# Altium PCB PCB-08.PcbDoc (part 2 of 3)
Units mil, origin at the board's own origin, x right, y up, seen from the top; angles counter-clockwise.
Board outline 2372.23 x 1978.53 mil, 4 copper layers (Top Layer, Plane-1, Plane-2, Bottom Layer), stack 84.834 mil thick; 206 components, 83 nets, 492 pads, 242 vias.
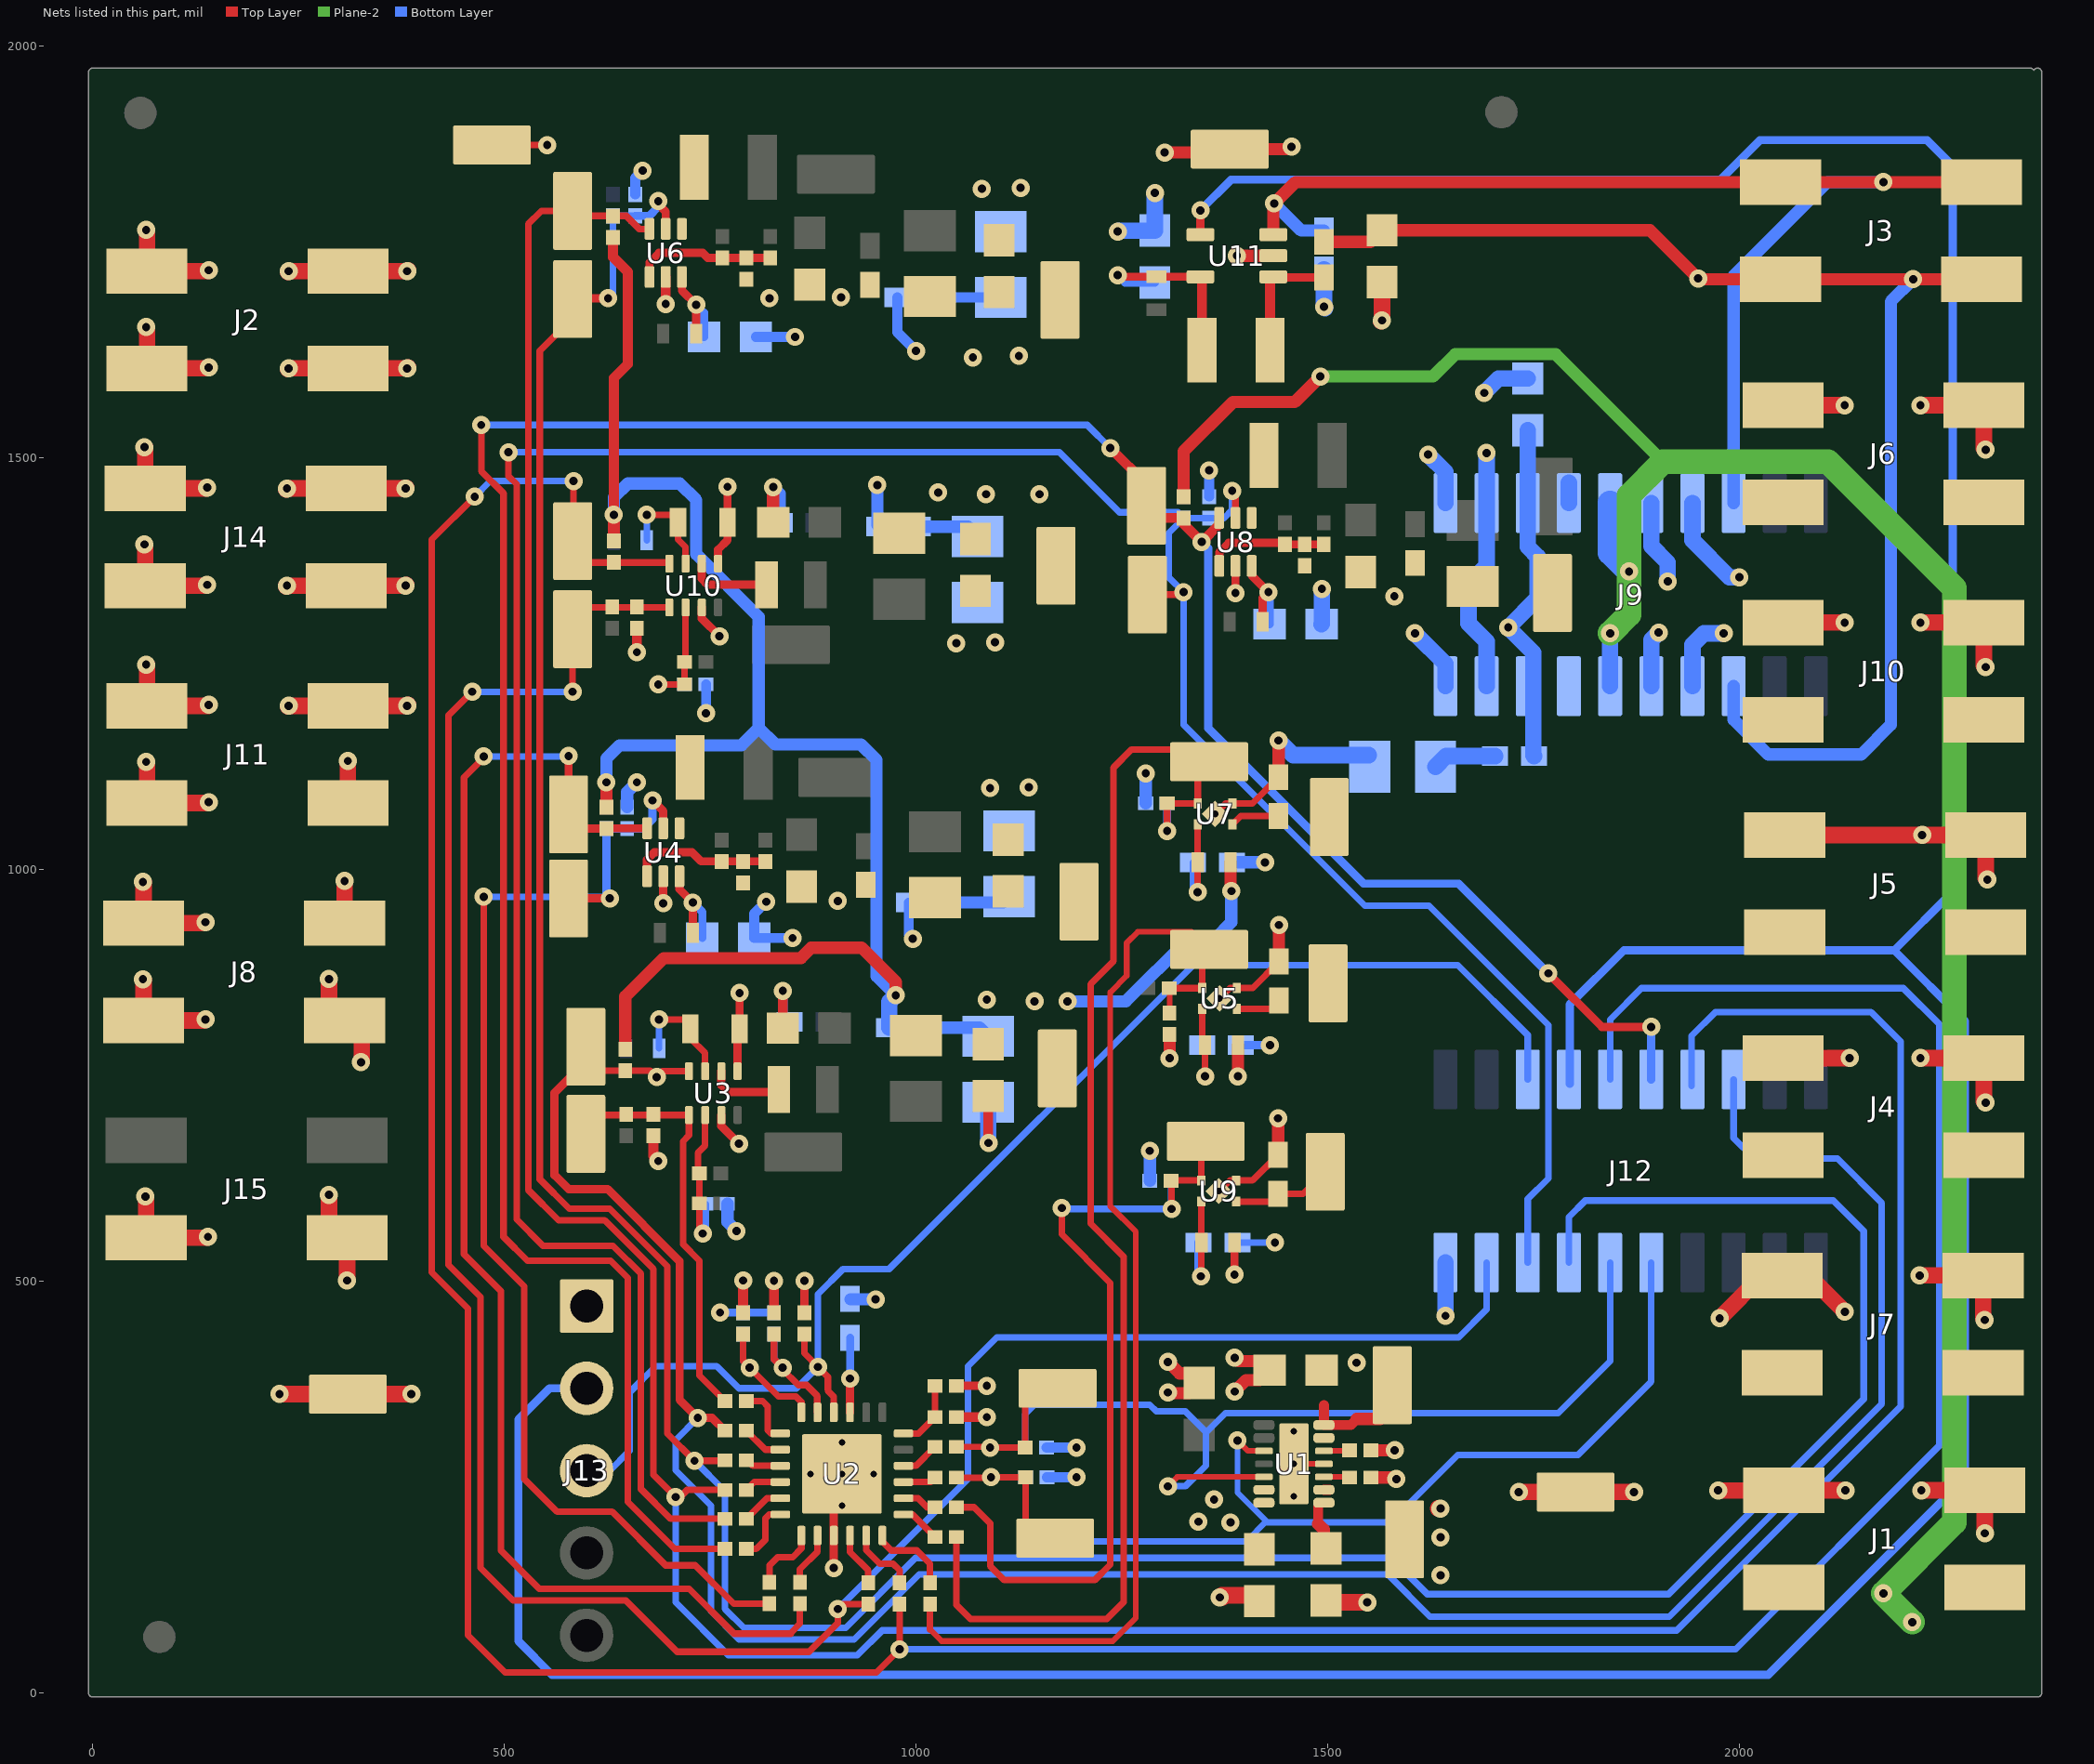
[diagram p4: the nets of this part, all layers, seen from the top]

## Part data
C1 C10 C13 C16 C20: library part CMP-0006203-2, "CAP, CERM, 0.01 uF, 10 V, +/- 10%, X7R, 0402", Cap_Case=0402, Manufacturer=AVX, Supplier Part Number 1=478-7890-1-ND, TempCo=X7R, Tolerance_%=10%, Value1=Unknown, Value2=10V, ValueDisplayed=0.01uF
C2 C11 C14 C17 C21: library part CMP-0007318-5, "CAP, CERM, 10 uF, 10 V, +/- 20%, X5R, 0603", Cap_Case=0603, Manufacturer=MuRata, TempCo=X5R, Tolerance_%=20%, Value1=Unknown, Value2=10V, ValueDisplayed=10uF
C3 C12 C15 C18 C22: library part CMP-0078699-1, "CAP, CERM, 47 µF, 10 V,+/- 20%, X5R, 0805", Cap_Case=0805, Manufacturer=MuRata, Supplier Part Number 1=490-9961-1-ND, TempCo=X5R, Tolerance_%=20%, Value2=10V, ValueDisplayed=47µF
C4: library part CMP-0007379-4, "CAP, CERM, 1 uF, 16 V, +/- 10%, X7R, 0603", Cap_Case=0603, Manufacturer=MuRata, Supplier Part Number 1=490-3900-1-ND, TempCo=X7R, Tolerance_%=10%, Value1="0.011 ohm", Value2=16V, ValueDisplayed=1uF
C5 C6 C25 C27 C32 C37 C42 C45: library part CMP-0064936-4, "CAP, CERM, 4.7 uF, 16 V,+/- 10%, X7R, 0603", Cap_Case=0603, Manufacturer=MuRata, TempCo=X7R, Tolerance_%=10%, Value1=Unknown, Value2=16V, ValueDisplayed=4.7uF
C7: library part CMP-0007365-4, "CAP, CERM, 1 uF, 10 V, +/- 10%, X7R, 0603", Cap_Case=0603, Manufacturer=MuRata, Supplier Part Number 1=490-3899-1-ND, TempCo=X7R, Tolerance_%=10%, Value1="0.011 ohm", Value2=10V, ValueDisplayed=1uF
C8 C9: library part CMP-0009636-3, "CAP, CERM, 1000 pF, 25 V, +/- 10%, X5R, 0201", Cap_Case=0201, Manufacturer=TDK, Supplier Part Number 1=445-1790-1-ND, TempCo=X5R, Tolerance_%=10%, Value1=Unknown, Value2=25V, ValueDisplayed=1000pF
C19: library part CMP-0064927-2, "CAP, CERM, 1 uF, 10 V,+/- 20%, X5R, 0402", Cap_Case=0402, Manufacturer=MuRata, Supplier Part Number 1=490-5409-1-ND, TempCo=X5R, Tolerance_%=20%, Value1=Unknown, Value2=10V, ValueDisplayed=1uF
C23 C41: library part CMP-0009765-1, "CAP, CERM, 120 pF, 25 V, +/- 10%, X7R, 0201", Cap_Case=0201, Manufacturer=MuRata, Supplier Part Number 1=490-3173-1-ND, TempCo=X7R, Tolerance_%=10%, Value1=Unknown, Value2=25V, ValueDisplayed=120pF
C24 C29 C36: library part CMP-0009669-4, "CAP, CERM, 6.8 pF, 50 V, +/- 2%, C0G/NP0, 0201", Cap_Case=0201, Manufacturer=MuRata, Supplier Part Number 1=GRM0335C1H6R8BA01D-ND, TempCo=C0G/NP0, Tolerance_%=2%, Value1=Unknown, Value2=50V, ValueDisplayed=6.8pF
C26 C28 C33 C38 C43: library part CMP-0007497-5, "CAP, CERM, 10 uF, 10 V, +/- 20%, X7R, 0603", Cap_Case=0603, Manufacturer=MuRata, Supplier Part Number 1=81-GRM188Z71A106MA3D, TempCo=X7R, Tolerance_%=20%, Value1=Unknown, Value2=10V, ValueDisplayed=10uF
C30 C31 C34 C35 C39 C40: library part CMP-0006563-2, "CAP, CERM, 1 uF, 10 V, +/- 10%, X5R, 0402", Cap_Case=0402, Manufacturer=MuRata, Supplier Part Number 1=490-3890-1-ND, TempCo=X5R, Tolerance_%=10%, Value1=Unknown, Value2=10V, ValueDisplayed=1uF
C44: library part CMP-0007052-4, "CAP, CERM, 1 uF, 35 V, +/- 10%, X7R, 0603", Cap_Case=0603, Manufacturer=TDK, Supplier Part Number 1=445-7414-1-ND, TempCo=X7R, Tolerance_%=10%, Value1=Unknown, Value2=35V, ValueDisplayed=1uF
D1: library part CMP-0028616-2, "Diode, Schottky, 40 V, 0.25 A, SOD-523", Manufacturer="ON Semiconductor", Supplier Part Number 1=NSR0240V2T1GOSCT-ND, Value1=0.25A, Value2=0.7V
FID1 FID2 FID3 FID4 FID5 FID6: "Fiducial mark.  There is nothing to buy or mount.", Manufacturer=N/A
H1 H2 H3 H4: "Bumpon, Hemisphere, 0.44 X 0.20, Clear", Manufacturer=3M, Supplier Part Number 1=SJ5303-7-ND
J1 J2 J3 J4 J5 J6 J7 J8 J10 J11 J14 J15: library part CMP-0075342-1, "Terminal Block, 3mm, 2-pole, Tin, SMD", Color=White, Current_A=3A, Manufacturer=WAGO, Supplier Part Number 1=38Y8605
J9 J12: library part CMP-0081743-1, "Receptacle, 1.27mm, 10x2, Gold with Tin tail, SMT", Color=Black, Current_A=3.1A, Manufacturer=Samtec, Supplier Part Number 1=SAM9848-ND
J13: library part CMP-0075485-1, "Header, 100mil, 5x1, Gold, TH", Manufacturer=Samtec, Supplier Part Number 1=SAM8737-ND
L1 L2 L3 L4 L5: library part CMP-0003136-1, "Ferrite Bead, 600 ohm @ 100 MHz, 2.1 A, 0805", Manufacturer="Wurth Elektronik", Supplier Part Number 1=732-6126-1-ND, Value1="0.043 ohm", Value2=2.1A, ValueDisplayed="600 ohm"
L6 L10: library part CMP-0064308-1, "Inductor, Shielded, 1 uH, 1.8 A, 0.078 ohm, SMD", Manufacturer="Wurth Elektronik", Supplier Part Number 1=732-9707-1-ND, Value1="0.078 ohm", Value2=1.8A, ValueDisplayed=1uH
L7 L8 L9: library part CMP-0058936-1, "Inductor, Shielded, 2.2 uH, 2.6 A, 0.07 ohm, SMD", Manufacturer="MuRata Toko", PartNumber=DFE252012P-2R2M{}P2, Value1="0.07 ohm", Value2=2.6A, ValueDisplayed=2.2uH
L11: library part CMP-0058942-1, "Inductor, Shielded, Metal Composite, 4.7 uH, 1.4 A, 0.165 ohm, AEC-Q200 Grade 1, SMD", Manufacturer="MuRata Toko", Value1="0.165 ohm", Value2=1.4A, ValueDisplayed=4.7uH
LBL1: library part THT-14-423-10, "Thermal Transfer Printable Labels, 0.650\" W x 0.200\" H - 10,000 per roll", Alternate Manufacturer=-, Manufacturer=Brady, Supplier Part Number 1=2065596
Logo2: library part Pb-Free
Logo3: library part FCC_disclaimer, "FCC_disclaimer"
R1 R2 R3 R4 R5 R6 R8 R9 R10 R11 R12 R14 R15 R16 R17 R18 R20 R21 R22 R25 R26 R27 R28 R29 R44 R45 R48 R50 R51 R56 R57 R58 R62 R66 R70: library part CMP-0027293-2, "RES, 100 k, 1%, 0.05 W, 0201", Manufacturer="Yageo America", Power_W=50mW, Supplier Part Number 1=311-100KMCT-ND, TempCo="200 ppm/C", Tolerance_%=1%, Value2=0.05W, Value_Code=100k
R7 R13 R19 R33 R52: library part CMP-0026635-1, "RES, 0.33, 1%, 0.125 W, 0402", Manufacturer=Panasonic, Power_W=125mW, Supplier Part Number 1=P.33AKCT-ND, TempCo="250 ppm/C", Tolerance_%=1%, Value2=0.125W, Value_Code=R330, ValueDisplayed=0.33
R23 R24 R30 R31 R32 R34 R35 R36 R37 R38 R39 R40 R41 R42 R43 R46 R47 R49: library part CMP-0027008-4, "RES, 0, 5%, 0.05 W, 0201", Manufacturer=Vishay-Dale, Power_W=50mW, Supplier Part Number 1=72M6743, TempCo=ppm/C, Tolerance_%=5%, Value2=0.05W, Value_Code=0000, ValueDisplayed=0
R53 R54 R59 R60 R63 R64 R67 R68 R71: library part CMP-0027004-2, "RES, 0, 5%, 0.063 W, 0402", Manufacturer="Yageo America", Power_W=63mW, Supplier Part Number 1=311-0.0JRCT-ND, TempCo="200 ppm/C", Tolerance_%=5%, Value2=0.063W, Value_Code=0000, ValueDisplayed=0
R55: library part CMP-0027710-1, "RES, 453 k, 1%, 0.05 W, 0201", Manufacturer="Yageo America", Power_W=50mW, Supplier Part Number 1=YAG2680CT-ND, TempCo="200 ppm/C", Tolerance_%=1%, Value2=0.05W, Value_Code=453k
R61: library part CMP-0027976-1, "RES, 200 k, 1%, 0.05 W, 0201", Manufacturer="Yageo America", Power_W=50mW, Supplier Part Number 1=603-RC0201FR-7D200KL, TempCo="200 ppm/C", Tolerance_%=1%, Value2=0.05W, Value_Code=200k
R65: library part CMP-0027330-2, "RES, 124 k, 1%, 0.05 W, 0201", Manufacturer="Yageo America", Power_W=50mW, Supplier Part Number 1=311-124KMCT-ND, TempCo="200 ppm/C", Tolerance_%=1%, Value2=0.05W, Value_Code=124k
R69: library part CMP-0027891-1, "RES, 82.5 k, 1%, 0.05 W, 0201", Manufacturer="Yageo America", Power_W=50mW, Supplier Part Number 1=YAG2815CT-ND, TempCo="200 ppm/C", Tolerance_%=1%, Value2=0.05W, Value_Code=82k5, ValueDisplayed=82.5k
R72: library part CMP-0026747-1, "RES, 2.20, 1%, 0.2 W, 0402", Manufacturer=Vishay-Dale, Power_W=200mW, Supplier Part Number 1=RCS04022R20FKED-ND, TempCo="100 ppm/C", Tolerance_%=1%, Value2=0.2W, Value_Code=2R20, ValueDisplayed=2.20
TP1 TP2 TP3 TP4 TP5 TP6 TP7 TP8 TP9 TP10 TP11 TP12 TP13 TP14 TP15 TP16 TP17 TP18 TP19 TP20 TP21 TP22 TP23 TP24 TP25 TP26 TP27 TP28 TP29 TP30 TP31 TP32 TP33 TP34: library part CMP-0067620-1, "PC Test Point, SMT", Manufacturer="TE Connectivity", Supplier Part Number 1=A106145CT-ND
U1: library part CMP-0073686-3, "5.5V, 6A, 14mO, Dual Load Switch with Adj. Rise Time & Optional QOD, DPU0014A (WSON-14)", Alternate Manufacturer="Texas Instruments", Alternate PartNumber=TPS22976DPUT
U2: library part CMP-0043177-2, "Remote 16-Bit I2C and SMBus, Low-Power I/O Expander with Interrupt Output and Config Register, 1.65 to 5.5 V, -40 to 85 degC, 24-pin QFN (RTW), Green (RoHS & no Sb/Br)", 5V Tolerant I/O=Yes, Manufacturer="Texas Instruments", Max Frequency(kHz)=400
U3 U10: library part CMP-0065148-3, "1A Step-Down Converter With 1% Accuracy, DLC0008A (VSON-HR-8)", Alternate Manufacturer="Texas Instruments"
U4 U6 U8: library part CMP-0013406-3, "1-A High Efficiency Step-Down Converter in SOT Package, DRL0006A (SOT-6)", Alternate Manufacturer="Texas Instruments"
U5: library part CMP-0079104-2, "200-mA, Small Size, Low-Dropout Linear Voltage Regulator, DQN0004A (X2SON-4)", Alternate Manufacturer="Texas Instruments"
U7 U9: library part CMP-0079107-2, "200-mA, Small Size, Low-Dropout Linear Voltage Regulator, DQN0004A (X2SON-4)", Alternate Manufacturer="Texas Instruments"
U11: library part CMP-0073719-2, "TPS61169 38-V High-Current Boost WLED Driver, DCK0005A (SOT-SC70-5)", Alternate Manufacturer="Texas Instruments"
ZZ1: library part AssemblyNoteLabel, Alternate Manufacturer=-
ZZ2 ZZ3 ZZ4: library part AssemblyNote, Alternate Manufacturer=-

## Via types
v1: diameter 22, hole 10, Top Layer to Bottom Layer, 231 vias
v2: diameter 19.68, hole 7.87, Top Layer to Bottom Layer, 8 vias
v3: diameter 18, hole 8, Top Layer to Bottom Layer, 3 vias

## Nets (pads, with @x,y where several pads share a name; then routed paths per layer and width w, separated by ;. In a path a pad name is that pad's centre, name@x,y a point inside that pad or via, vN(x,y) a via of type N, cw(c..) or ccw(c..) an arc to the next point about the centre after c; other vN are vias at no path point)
1V1: C21.1 J9.3 J9.4 J14.2 L5.2 R52.2 TP22.1 | length 625.7
  Top Layer w20: v1(63,1513.05) 63.95,1512.1 J14.2@63.95,1462.95 137.9,1462.95 v1(139,1464.05) ; v1@235.05,1461.95 v1(236.05,1462.95) J14.2@308.05,1462.95 v1(380.05,1462.95) v1@381.05,1463.95
  Bottom Layer w15: v1(953,1467) 953,1418.64 R52.2@955.13,1416.5
  Bottom Layer w20: J9.3@1693,1222.78 1693,1277.16 1671,1299.16 1671,1347 1693,1369 J9.4@1693,1445.22 v1(1693,1506)
  other v1: 1085,1456 1150,1456 1027,1458
1V2: C17.1 J10.2 L4.2 R33.2 TP19.1 | length 45.9
  Bottom Layer w12: R33.2@991.38,960 991.38,920.62 v1(996,916)
1V8: C11.1 J2.2 J9.7 J9.8 L2.2 R13.2 TP11.1 | length 371.7
  Top Layer w20: v1(65,1777) 65.95,1776.05 J2.2@65.95,1726.9 139.9,1726.9 v1(141,1728) ; v1@237.05,1725.9 v1(238.05,1726.9) J2.2@310.05,1726.9 v1(382.05,1726.9) v1@383.05,1727.9
  Bottom Layer w12: R13.2@977.38,1695 977.38,1652.62 v1(1000,1630)
  Bottom Layer w20: J9.8@1793,1445.22 J9.8@1793,1469.74
  other v1: 1069,1622 1125,1624
1V35: C14.1 J6.2 J9.5 J9.6 L3.2 R19.2 TP15.1 | length 428.2
  Bottom Layer w20: C14.1@1743,1533.5 J9.6@1743,1445.22 1743,1392.01 1755,1380.01 1755,1329.79 v1(1719.32,1294.11) 1749.89,1263.54 1749.89,1138.73 R19.2@1750.62,1138
3V3: C2.1 C6.1 C19.1 J1.2 J9.9 J9.10 L1.2 R3.1 R6.1 R7.2 R12.1 R16.1 R20.1 R27.2 R28.2 R29.2 R48.1 R59.1 R63.1 R67.1 TP4.1 U1.6 U1.7 U2.21 | length 5515.4
  Top Layer w8: v1(1386.81,508.19) v1@1387,508
  Top Layer w10: R48.1@864.5,461.99 v1(864.5,500.5) v1@865,501 ; U2.21@919.84,340.8 v1(919.84,381.84) ; R27.2@1048.99,373 v1(1086,373) ; v1@1382.12,971.39 v1@1383,970.51 ; v1(1386.81,508.19) R67.1@1386.81,547
  Top Layer w12: R6.1@632,1768.01 632,1744 650,1726 650,1614 633,1597 v1(633,1431)
  Top Layer w15: R16.1@624,1075.99 v1(624,1106) ; R20.1@633,1398.99 v1(633,1431) ; R3.1@647,781.99 647,846 693.5,892.5 860.15,892.5 872.65,905 934,905 975.38,863.62 v1(975.38,847.38) ; R12.1@1325,1452.99 1325,1508 1385,1568 1460,1568 v1(1491,1599) ; v1@1382.12,971.39 R63.1@1382.12,1008.81 ; v1(1391,749) R59.1@1391,786.81
  Plane-2 w15: v1(1491,1599) 1628,1599 1655,1626 1777,1626 1907.37,1495.63
  Plane-2 w30: v1(1843,1287) 1866,1310 v1(1866,1362) 1866,1454.26 1907.37,1495.63 2107.37,1495.63 2261,1342 2261,207 v1(2175,121) v1(2210,86)
  Bottom Layer w10: v1(762.01,461.99) R29.2@790.01,461.99 R28.2@827.5,461.99 ; v1@920,382 C19.1@920,431.38
  Bottom Layer w15: v1(624,1106) 624,1135 640,1151 788,1151 809,1172 ; v1(633,1431) 633,1452 650,1469 713,1469 733,1449 733,1383 809,1307 809,1172 ; v1(975.38,847.38) 952,870.76 952,1133 933,1152 829,1152 809,1172 ; v1(1184,840) 1255,840 1331,916 1363,916 1383,936 v1(1383,974)
  Bottom Layer w20: R7.2@967.38,808 967.38,839.38 v1(975.38,847.38) ; J9.9@1843,1222.78 v1(1843,1287)
  Bottom Layer w30: J9.10@1843,1445.22 1843,1385 v1(1866,1362)
  other v1: 1382,207 1343,208 1362,235 1144,840 1086,842
EN_1V1: J12.3 R14.2 R17.1 R40.1 TP12.1 U10.1 | length 3050.2
  Top Layer w8: v1(461,1216) 432.31,1187.31 432.31,519.69 471,481 471,152 510.52,112.48 647.52,112.48 710,50 870,50 905,85 v1(905,102) 911,108 R40.1@942,108 ; v1(583,1216) TP12.1@583,1292 583,1307 594.43,1318.43 U10.1@700.47,1318.43
  Bottom Layer w8: v1(461,1216) v1(583,1216) ; v1(905,102) 1063,260 1063,397 1098,432 1659,432 1693,466 J12.3@1693,522.78
EN_1V2: R9.2 R11.1 R35.1 TP8.1 U4.5 | length 1498.4
  Top Layer w8: v1(475,967) 475,543 524,494 524,260 564,220 631,220 696,155 732.01,155 778.5,108.5 R35.1@822,108.5
  Top Layer w10: TP8.1@578,965 v1(628,965) ; v1(680,1084) 693,1071 U4.5@693,1050.13
  Bottom Layer w8: v1(475,967) v1@626,967
  Bottom Layer w10: v1(628,965) 626,967 624,969 R9.2@624,1050.01 R11.1@649,1050.01 668.87,1050.01 680,1061.13 v1(680,1084)
EN_1V8: J12.7 R2.2 R5.1 R30.1 TP2.1 U6.5 | length 4206.3
  Top Layer w8: TP2.1@583,1693 583,1670 543,1630 543,624 579,588 628,588 698,518 698,315 v1(731,282) 768.5,282 R30.1@768,282.5
  Top Layer w10: TP2.1@583,1693 584,1694 v1(626,1694) ; v1(687,1812) 685,1812 684,1811 696,1799 U6.5@696,1778.13
  Bottom Layer w8: v1(626,1694) 632,1700 R2.2@632,1794.01 R5.1@659,1794.01 ; v1(731,282) 768,245 768,102 791,79 914.53,79 999.53,164 1577,164 1621,120 1914,120 2151,357 2151,561 2114,598 1813,598 1793,578 J12.7@1793,522.78
  Bottom Layer w10: R5.1@659,1794.01 676.01,1794.01 687,1805 v1(687,1812)
EN_1V35: J12.5 R8.2 R10.1 R32.1 TP7.1 U8.5 | length 3670.6
  Top Layer w8: v1(505,1507) 505,1478 515,1468 515,575 547,543 632,543 666,509 666,247.47 701.98,211.5 R32.1@768.01,211.5 ; TP7.1@1281,1334 1322,1334 v1(1325,1337) ; v1(1384,1460) 1388,1456 U8.5@1388,1427.13
  Bottom Layer w8: v1(505,1507) 1174,1507 1247.06,1433.94 1318.07,1433.94 R8.2@1325,1427.01 ; v1(1384,1460) 1384,1437 1374.01,1427.01 R10.1@1356,1427.01 R8.2@1325,1427.01 ; J12.5@1743,522.78 1743,600 1768,625 1768,811 1623,956 1545,956 1325,1176 v1(1325,1337) 1307,1355 1307,1409.01 R8.2@1325,1427.01
EN_3V3: R1.2 R4.1 R23.1 TP1.1 U3.1 | length 506.3
  Top Layer w8: TP1.1@599,679 621.93,701.93 U3.1@724.23,701.93 724.23,677.23 717,670 717,545 737,525 737,385.49 R23.1@767.99,354.5
EN_G3V3: J12.9 R45.2 R49.1 R51.1 TP21.1 U1.5 | length 1376.9
  Top Layer w7: R49.1@1049,299 v1@1089,299 ; v1(1306,251) 1317.46,262.46 U1.5@1422.58,262.46
  Top Layer w8: v1@1089,299 v1(1090,298) R45.2@1132.5,298 1132.5,361.5 1141,370 TP21.1@1172,370
  Bottom Layer w8: v1(1090,298) R51.1@1132.5,298 1132.5,338.5 1144,350 1284,350 1292,342 1327,342 1352,317 1352,316 ; v1(1306,251) 1327,251 1352,276 1352,316 ; J12.9@1843,522.78 1843,403 1780,340 1376,340 1352,316
EN_G5V: J12.11 R44.2 R47.1 R50.1 TP20.1 U1.3 | length 1437.1
  Top Layer w7: v1(1390.42,306.72) 1403.17,293.96 U1.3@1422.58,293.96
  Top Layer w8: R47.1@1048.99,261.5 1090.5,261.5 v1(1091,262) R44.2@1133.01,262 1133.01,199.99 1145,188 TP20.1@1169,188
  Bottom Layer w7: v1(1390.42,306.72) 1390.42,243.58 1425.5,208.5 ; 1401,184 1425.5,208.5 ; 1426.74,207.26 1425.5,208.5
  Bottom Layer w8: v1(1091,262) R50.1@1133.01,262 1133.01,194.99 1144,184 1401,184 ; 1426.74,207.26 1576.26,207.26 1658,289 1804,289 1893,378 J12.11@1893,522.78
EN_L1V8A: R21.2 R25.1 R43.1 TP17.1 U7.3 | length 1634.9
  Top Layer w8: R43.1@1048.99,189.5 1048.99,107.01 1066,90 1232,90 1252,110 1252,530 1212,570 1212,861 1240,889 1240,1124 1262,1146 1341,1146 TP17.1@1356,1131 1342.26,1117.26 U7.3@1342.26,1080.4 1342.17,1080.5 R21.2@1304.99,1080.5 v1(1304.99,1046.99)
  Bottom Layer w10: v1(1304.99,1046.99) R25.1@1304.99,1080.5
EN_L1V8B: R22.2 R26.1 R46.1 TP18.1 U9.3 | length 1012.2
  Top Layer w8: R46.1@1048.99,225.5 1070.5,225.5 1090,206 1090,154 1107,137 1217,137 1236,156 1236,498 1177,557 v1(1177,589) ; v1@1307.87,585.4 v1(1310.39,587.91) R22.2@1310.39,622.4 ; R22.2@1309.98,622 R22.2@1310.39,622.4 ; TP18.1@1352,670 1346.59,664.59 U9.3@1346.59,622.4 R22.2@1310.39,622.4
  Bottom Layer w8: v1(1177,589) 1178.09,587.91 v1(1310.39,587.91) 1309.98,588.32 R26.1@1309.98,622
EN_L2V8: R15.2 R18.1 R42.1 TP13.1 U5.3 | length 1374.6
  Top Layer w7: 1017,77 1031,63 1239,63 1267,91 1267,560 1236,591 1236,851 1256,871 1256,910.99 1269.51,924.5 1334.5,924.5 TP13.1@1356,903 ; R15.2@1307.5,856 1308,855.5 R18.1@1308,825.99
  Top Layer w8: 1017,77 R42.1@1017,108 ; R15.2@1307.5,856 1347.19,856 U5.3@1347.59,856.4 1347.59,894.59 TP13.1@1356,903
G3V3: C7.1 J9.11 J9.12 J11.2 TP9.1 U1.8 U1.9 | length 500.6
  Top Layer w12: 1488.46,205.26 U1.8@1488.46,225.81 ; U1.9@1495.42,246.72 U1.9@1502.28,246.72
  Top Layer w15: 1488.46,205.26 1495.42,198.3 C7.1@1495.42,183.21
  Top Layer w20: v1(65,1249) 65.95,1248.05 J11.2@65.95,1198.89 139.9,1198.89 v1(141,1200) ; v1@237.05,1197.89 v1(238.05,1198.89) J11.2@310.05,1198.89 v1(382.05,1198.89) v1@383.05,1199.89 ; v1@1634,224 v1(1637,224)
  Bottom Layer w20: J9.11@1893,1222.78 1893,1279 v1(1902,1288) ; J9.12@1893,1445.22 1893,1393 1913,1373 v1(1913,1350)
  other v1: 1637,143 1637,189
G5V: C4.1 J8.2 J9.13 J9.14 TP6.1 U1.13 U1.14 | length 534.5
  Top Layer w12: 1495.42,349.42 U1.14@1495.42,325.46 1528.16,325.46 1535.42,332.72
  Top Layer w15: 1535.42,332.72 1563.72,332.72 1578.42,347.42 TP6.1@1578.42,373.72
  Top Layer w20: v1(61,985.05) 61.95,984.1 J8.2@61.95,934.95 135.9,934.95 v1(137,936.05) ; v1(306,986.16) 306.05,986.12 J8.2@306.05,934.95
  Bottom Layer w20: J9.13@1943,1222.78 1943,1273 1957,1287 v1(1981,1287) ; J9.14@1943,1445.22 1943,1400 1988,1355 v1(2000,1355)
  other v1: 1535,401
GND: C1.2 C2.2 C3.2 C4.2 C5.2 C6.2 C7.2 C8.2 C9.2 C10.2 C11.2 C12.2 C13.2 C14.2 C15.2 C16.2 C17.2 C18.2 C19.2 C20.2 C21.2 C22.2 C25.2 C26.2 C27.2 C28.2 C30.2 C31.2 C32.2 C33.2 C34.2 C35.2 C37.2 C38.2 C39.2 C40.2 C42.2 C43.2 C44.2 C45.2 J1.1 J2.1 J4.1 J5.1 J6.1 J7.1 J8.1 J9.1 J9.2 J10.1 J11.1 J12.1 J13.1 J14.1 J15.1 R4.2 R5.2 R10.2 R11.2 R17.2 R18.2 R25.2 R26.2 R37.1 R38.1 R39.1 R50.2 R51.2 R57.2 R58.2 R62.2 R66.2 R70.2 R72.2 TP23.1 TP24.1 TP25.1 TP26.1 U1.11 U1.15@1459,278.21 U2.9 U2.25 U3.3 U3.5 U4.2 U5.2 U5.5 U6.2 U7.2 U7.5 U8.2 U9.2 U9.5 U10.3 U10.5 U11.2 | length 6313.9
  Top Layer w7: v2(1459,278.21) U1.11@1495.42,278.21
  Top Layer w8: TP23.1@485,1880 v1(552,1880) ; v3(1363.33,1067.61) 1376.12,1080.4 U7.2@1384.39,1080.4 1408.5,1080.4 C35.2@1440.33,1112.23 ; v3(1368.66,843.61) 1381.45,856.4 U5.2@1389.72,856.4 1408.97,856.4 C31.2@1440.8,888.23 ; U9.5@1368.84,609.61 1381.63,622.4 U9.2@1388.72,622.4 1408.77,622.4 C40.2@1439.8,653.43 ; v1(1439.8,698.01) v1@1440,698.2 ; v1(1440.33,1156.8) v1@1440.53,1157 ; v1(1440.8,932.8) v1@1441,933
  Top Layer w10: v1(693,959) U4.2@693,991.87 ; U10.3@739.84,1318.43 739.84,1304.9 v1(761.24,1283.5) ; U10.5@759.53,1371.57 759.53,1388.53 771,1400 C42.2@771,1422 v1(771,1465) ; U3.3@763.6,701.93 763.6,688.4 v1(785,667) ; U3.5@783.28,755.08 C25.2@783.28,804.03 ; C25.2@785.76,806.5 v1(785.76,850.24) ; v1(900.16,151.84) U2.9@900.16,191.2 900.16,227.61 v2(910,227.61) ; v1(1388,1336) U8.2@1388,1368.87
  Top Layer w12: v1(661,1264) R17.2@661,1293.01 ; R4.2@681,677.01 681,652 v1(687,646) ; v1(696,1687) U6.2@696,1719.87 ; R39.1@790.01,461.99 v1(790.01,501.01) ; R38.1@827.5,461.99 v1(827.5,500.5) ; C26.2@838.26,807.5 v1(838.26,852.74) ; R37.1@1049,335 v1(1086,335) ; C2.2@1087.76,725.01 1087.76,673.24 1088,673 v1@1089,674 ; v1@1974,246 v1(1974.11,246.11) ; v1(2127.84,1300.06) v1@2127.95,1299.94 ; v1(2127.84,1564) v1@2127.95,1563.89 ; v1(2128.89,246.11) v1@2129,246
  Top Layer w15: C43.2@826.5,1422 v1(826.5,1464.5) ; v1(1302,1871) 1377,1871 TP24.1@1381,1875 1453,1875 v1(1456,1878) ; v1(1306,365) 1307,364 1331.5,364 C5.2@1344,376.5 1332.5,388 1320,388 v1(1306,402) ; v1(1308,771) R18.2@1308,800.01 ; v1(1387,366) 1401,380 1417.5,380 C4.2@1429.5,392 1418.5,403 1391,403 v1(1387,407) ; v1(1389.66,1745.61) U11.2@1433.95,1745.61 ; C40.2@1439.8,653.43 v1(1439.8,698.01) ; C35.2@1440.33,1112.23 v1(1440.33,1156.8) ; C31.2@1440.8,888.23 v1(1440.8,932.8) ; C9.2@1552.41,261.72 1581.42,261.72 v1(1583.42,259.72) ; C8.2@1552.41,294.72 v1(1581.42,294.72)
  Top Layer w20: v1(61,866.94) 61.95,865.99 J8.1@61.95,816.84 135.9,816.84 v1(137,817.94) ; v1(63,1394.94) 63.95,1393.99 J14.1@63.95,1344.84 137.9,1344.84 v1(139,1345.94) ; v1(64.05,602.99) 65,602.04 J15.1@65,552.89 138.94,552.89 v1(140.05,553.99) ; v1(65,1130.89) 65.95,1129.94 J11.1@65.95,1080.78 139.9,1080.78 v1(141,1081.89) ; v1(65,1658.89) 65.95,1657.94 J2.1@65.95,1608.79 139.9,1608.79 v1(141,1609.89) ; v1(227,363) TP25.1@310,363 v1(387,363) ; v1@235.05,1343.84 v1(236.05,1344.84) J14.1@308.05,1344.84 v1(380.05,1344.84) v1@381.05,1345.84 ; v1@237.05,1607.79 v1(238.05,1608.79) J2.1@310.05,1608.79 v1(382.05,1608.79) v1@383.05,1609.79 ; v1(287,605) 287,572 290,569 292.98,569 J15.1@309.09,552.89 309.09,501.09 v1(309,501) ; v1(287,867) 287,835.88 J8.1@306.05,816.84 321.88,801 327,801 327,767 v1(326,766) ; v1(310,1132) J11.1@310.05,1080.78 J11.1@310.05,1080.78 ; v1@1372.7,116 v1(1369,116) 1371.5,118.5 1410,118.5 C6.2@1417,111.5 ; C7.2@1495.42,120.22 1505.64,110 v1(1548,110) ; v1@1565,1666 v1(1566,1667) C44.2@1566,1713.5 ; v1(1732,244) TP26.1@1801,244 v1(1872,244) ; v1@1974,246 2053.89,246 J1.1@2054,246.11 v1(2128.89,246.11) ; v1(1976,455) 2028.06,507.06 J7.1@2051.95,507.06 2083.94,507.06 v1(2128,463) ; J4.1@2052.95,771.06 v1(2133.94,771.06) ; J10.1@2052.95,1300.06 v1(2127.84,1300.06) ; J6.1@2052.95,1564 v1(2127.84,1564) ; J5.1@2055,1042 v1(2222,1042) J5.1@2299.09,1042 2299.09,989.89 v1(2301.09,987.89) ; v1(2218.95,507.06) J7.1@2296.05,507.06 2296.05,454.94 v1(2298.05,452.94) ; v1(2219.95,771.06) J4.1@2297.05,771.06 2297.05,718.94 v1(2299.05,716.94) ; v1(2219.95,1300.06) J10.1@2297.05,1300.06 2297.05,1247.94 v1(2299.05,1245.94) ; v1(2219.95,1564) J6.1@2297.05,1564 2297.05,1511.89 v1(2299.05,1509.89) ; v1(2221,246.11) J1.1@2298.09,246.11 v1(2298.09,194)
  Bottom Layer w8: C39.2@1390.43,547 v1(1436,547) v1@1438,549
  Bottom Layer w10: C30.2@1394.62,786.81 v1(1429.81,786.81) v1@1432,789
  Bottom Layer w12: R5.2@659,1819.99 659,1840 v1(668,1849) ; v1(744.99,1189.99) R70.2@744.99,1225 ; C32.2@805.5,1647 v1(853,1647) ; v1(818,961) 803.5,946.5 C27.2@803.5,917 v1(850,917) ; v1(838.26,852.74) 838.38,852.62 838.38,823 C1.2@846.38,815 ; C19.2@920,478.62 C19.2@920.62,478 ; v1@1087.76,668.24 v1(1088,668) ; R51.2@1158.49,298 v1(1195,298) ; R50.2@1158.99,262 v1(1195,262) ; R10.2@1356,1452.99 v1(1356,1485)
  Bottom Layer w15: R11.2@649,1075.99 649,1094 v1(661,1106) ; R57.2@770.99,594 770.99,572.02 v1(782.01,561) ; v1(826.5,1464.5) 834.38,1456.63 C20.2@834.38,1421 ; C19.2@920.62,478 v1(951,478) ; R25.2@1279.01,1080.5 v1(1279.01,1117.01) ; R26.2@1284,622 v1(1284,658.51) ; C34.2@1383.62,1008.81 v1(1423.81,1008.81)
  Bottom Layer w20: v1@1087.76,668.24 C3.2@1087.76,717.5 ; v1(1245,1775) 1246.1,1776.1 C45.2@1290.1,1776.1 v1(1290.1,1821.9) v1@1290,1822 ; v1(1440.33,1156.8) 1458.13,1139 C15.2@1550,1139 ; C37.2@1492.5,1298 1493,1298.5 v1(1493,1341) ; R72.2@1495.52,1728.98 v1(1495.52,1683.48) v1@1497,1682 ; v1(1606,1287) 1643,1250 J9.1@1643,1222.78 ; v1(1622,1504) 1643,1483 J9.2@1643,1445.22 ; v1(1643,458) J12.1@1643,522.78 ; v1(1690,1579) 1707.5,1596.5 C14.2@1743,1596.5
  other v1: 905,962 1090,1099 1137,1100 1049,1275 1096,1276 1581,1332 822,1694 909,1695 1080,1827 1127,1828
  other v2: 1459,238.84 871.61,266 910,266 948.39,266 910,304.39 1459,317.58
  other v3: 1367.66,609.61
I2C_INT: J12.6 J13.3 R48.2 U2.22 | length 1712.1
  Top Layer w8: R48.2@864.5,436.01 864.5,412.5 v1(881,396) 893,384 893,368.38 893.47,367.91 893.47,366.53 900.16,359.84 U2.22@900.16,340.8
  Bottom Layer w8: J13.3@600,270 628,270 652,294 652,365 684,397 758,397 785,370 855,370 v1(881,396) 881,484.47 911.53,515 967.53,515 1336.53,884 1658,884 1743,799 J12.6@1743,745.22
L1V8A: C35.1 J5.2 TP31.1 U7.1 | length 63
  Top Layer w8: U7.1@1384.39,1054.81 1394.56,1064.98 C35.1@1440.33,1064.98
  Top Layer w20: J5.2@2297.09,921.89 J5.2@2299.09,923.89
L1V8B: C40.1 J7.2 TP33.1 U9.1 | length 123.3
  Top Layer w8: U9.1@1388.72,596.81 1430.42,596.81 C40.1@1439.8,606.19 1470.19,606.19 TP33.1@1497,633
L2V8: C31.1 J4.2 TP29.1 U5.1 | length 55.3
  Top Layer w8: U5.1@1389.72,830.81 1430.63,830.81 C31.1@1440.8,840.98
LED_PWM: J12.8 J13.2 U11.4 | length 5408.4
  Top Layer w10: U11.4@1345.37,1771.2 v1(1345.37,1800.63)
  Bottom Layer w10: J13.2@600,370 555,370 517,332 517,63 558,22 2035,22 2274.05,261.05 2274.05,815.95 2188,902 ; v1(1345.37,1800.63) 1382.73,1838 1977,1838 2025,1886 2228,1886 2259,1855 2259,973 2188,902 ; J12.8@1794,740 1794,836 1860,902 2188,902
NetC3_1: C3.1 R7.1 | length 77.5
  Bottom Layer w15: R7.1@1014.62,808 1077.26,808 C3.1@1087.76,797.5
NetC8_1: C8.1 U1.12 | length 31.3
  Top Layer w7: U1.12@1495.42,293.96 1525.67,293.96 C8.1@1526.43,294.72
NetC9_1: C9.1 U1.10 | length 31.3
  Top Layer w7: U1.10@1495.42,262.46 1525.68,262.46 C9.1@1526.43,261.72
NetC12_1: C12.1 R13.1 | length 78.4
  Bottom Layer w12: R13.1@1024.62,1695 C12.1@1103,1695
NetC15_1: C15.1 R19.1 | length 77.8
  Bottom Layer w20: C15.1@1631,1125 1644,1138 R19.1@1703.38,1138
NetC18_1: C18.1 R33.1 | length 77.3
  Bottom Layer w15: R33.1@1038.62,960 1106,960 C18.1@1113,967
NetC22_1: C22.1 R52.1 | length 77.3
  Bottom Layer w15: R52.1@1002.38,1416.5 1062.76,1416.5 C22.1@1074.76,1404.5
NetC23_2: C23.2 R55.2 R57.1 U3.2 | length 186.1
  Top Layer w8: v1@737.01,557.99 C23.2@737.01,594.5 R55.2@737.01,631 735,633.01 735,656 743.91,664.91 U3.2@743.91,701.93
  Bottom Layer w8: v1(741.02,557.99) 745.01,561.98 R57.1@745.01,594
NetC24_2: C24.2 R56.2 R58.1 U4.1 | length 172.3
  Top Layer w10: U4.1@673.31,991.87 673.31,1012.31 682,1021 728,1021 738.99,1010.01 C24.2@764,1010.01 R58.1@790,1009.99 R56.2@817,1010.01
NetC25_1: C25.1 R53.2 U3.7 | length 143.2
  Top Layer w8: v1(688,818) 725.76,818 C25.1@725.76,806.5 725.76,795.24 743.91,777.09 U3.7@743.91,755.08
  Bottom Layer w8: R53.2@688,783 v1(688,818)
NetC27_1: C27.1 R54.2 U4.3 | length 123.4
  Top Layer w10: U4.3@712.68,991.87 712.68,976.32 v1(729,960) R54.2@729,923
  Bottom Layer w10: v1(729,960) 740.5,948.5 C27.1@740.5,917
NetC29_2: C29.2 R61.2 R62.1 U6.1 | length 171.4
  Top Layer w10: U6.1@676.31,1719.87 676.31,1737.31 688,1749 741,1749 746.99,1743.01 C29.2@765,1743.01 R62.1@794,1742.99 R61.2@823,1743.01
NetC30_1: C30.1 R59.2 U5.4 | length 122.5
  Top Layer w8: U5.4@1347.59,830.81 1347.59,790.22 R59.2@1351,786.81 v1(1351,749)
  Bottom Layer w8: C30.1@1347.38,786.81 1351,783.19 v1(1351,749)
NetC32_1: C32.1 R60.2 U6.3 | length 105.5
  Top Layer w10: U6.3@715.68,1719.87 715.68,1703.31 v1(733,1686) R60.2@733,1651
  Bottom Layer w10: C32.1@742.5,1647 742.5,1676.5
NetC34_1: C34.1 R63.2 U7.4 | length 123.4
  Top Layer w8: v1@1340.31,970.81 v1(1342.12,972.62) R63.2@1342.12,1008.81 1342.12,1054.66 U7.4@1342.26,1054.81
  Bottom Layer w8: C34.1@1336.38,1008.81 1336.38,978.36 v1(1342.12,972.62)
NetC36_2: C36.2 R65.2 R66.1 U8.1 | length 148.8
  Top Layer w10: U8.1@1368.31,1368.87 1368.31,1385.37 1379.94,1397 1446.01,1397 C36.2@1448,1395.01 R66.1@1472,1394.99 R65.2@1495,1395.01
NetC37_1: C37.1 R64.2 U8.3 | length 106.8
  Top Layer w10: U8.3@1407.68,1368.87 1407.68,1357.32 v1(1428,1337) ; R64.2@1421,1301 v1@1421,1330
  Bottom Layer w10: C37.1@1429.5,1298 v1@1429.5,1335.5
NetC39_1: C39.1 R67.2 U9.4 | length 130.6
  Top Layer w8: v1@1345,509 1346.59,510.59 U9.4@1346.59,596.81
  Bottom Layer w10: C39.1@1343.19,547 1343.19,508.81 v1(1346,506)
NetC41_2: C41.2 R69.2 R70.1 U10.2 | length 157.9
  Top Layer w8: v1(687,1225) R69.2@719.01,1225 C41.2@719.01,1252 720.16,1253.15 U10.2@720.16,1318.43
  Bottom Layer w8: v1(687,1225) R70.1@719.01,1225
NetC42_1: C42.1 R68.2 U10.7 | length 128.4
  Top Layer w8: v1(673,1431) 702,1431 C42.1@711,1422 711,1401 720.16,1391.84 U10.7@720.16,1371.57
  Bottom Layer w8: R68.2@673,1400 v1(673,1431) v1@674,1430
NetC45_1: C45.1 L11.1 R71.2 U11.5 | length 239.9
  Top Layer w10: v1(1245,1722) 1246.98,1720.02 U11.5@1345.37,1720.02 U11.5@1347.32,1718.06
  Top Layer w12: L11.1@1347.32,1630.87 U11.5@1347.32,1718.06
  Bottom Layer w10: v1(1245,1722) 1253.89,1713.11 C45.1@1290.1,1713.11
NetD1_2: D1.2 L11.2 U11.1 | length 145.9
  Top Layer w10: U11.1@1434.82,1719.14 D1.2@1495.52,1719.14
  Top Layer w12: L11.2@1430,1630.87 U11.1@1430,1716.06
NetL6_1: L6.1 U3.6 | length 91.3
  Top Layer w10: U3.6@763.6,755.08 763.6,738.4 772,730 830.47,730 L6.1@833.47,733
NetL7_1: L7.1 U4.4
NetL8_1: L8.1 U6.4
NetL9_1: L9.1 U8.4
NetL10_1: L10.1 U10.6 | length 100
  Top Layer w10: U10.6@739.84,1371.57 739.84,1353.16 747,1346 L10.1@818.47,1346
NetR23_2: R23.2 U2.1 | length 74.5
  Top Layer w8: R23.2@793.98,354.5 813.5,354.5 820,348 820,319 823.79,315.21 U2.1@835.2,315.21
NetR24_2: R24.2 U2.2 | length 50.7
  Top Layer w8: R24.2@793.98,318.5 816.94,295.53 U2.2@835.2,295.53
NetR27_1: R27.1 R37.2 U2.18 | length 84.4
  Top Layer w8: U2.18@984.8,315.21 1003.23,315.21 R37.2@1023.02,335 R27.1@1023.01,373
NetR28_1: R28.1 R38.2 U2.23 | length 168.4
  Top Layer w8: R38.2@827.5,436.01 827.5,405.5 v1(838,395) 838,393 857,374 867,374 879.47,361.53 879.47,360.73 880,360.2 880,341.28 U2.23@880.47,340.8
  Bottom Layer w8: R28.1@827.5,436.01 827.5,405.5 v1(838,395)
NetR29_1: R29.1 R39.2 U2.24 | length 181.8
  Top Layer w8: R39.2@790.01,436.01 790.01,403 v1(798.01,395) 833.01,360 854,360 860.79,353.21 U2.24@860.79,340.8
  Bottom Layer w8: R29.1@790.01,436.01 790.01,403 v1(798.01,395) v1@798.5,395.5
NetR30_2: R30.2 U2.3 | length 43.9
  Top Layer w8: R30.2@794.49,283 801.65,275.84 U2.3@835.2,275.84 U2.3@835.04,276
NetR31_2: R31.2 U2.4 | length 45.2
  Top Layer w8: R31.2@793.98,246.5 803.65,256.16 U2.4@835.2,256.16
NetR32_2: R32.2 U2.5 | length 51.6
  Top Layer w8: R32.2@793.99,211.5 818.97,236.47 U2.5@835.2,236.47
NetR34_2: R34.2 U2.6 | length 73.7
  Top Layer w8: R34.2@793.99,175 806,175 817,186 817,212 821.79,216.79 U2.6@835.2,216.79
NetR35_2: R35.2 U2.7 | length 83.4
  Top Layer w8: R35.2@822,134.49 822,155 832,165 850.22,165 860.79,175.57 U2.7@860.79,191.2
NetR36_2: R36.2 U2.8 | length 65.6
  Top Layer w8: R36.2@859,134.49 859,150 880.47,171.47 U2.8@880.47,191.2
NetR40_2: R40.2 U2.10 | length 66.4
  Top Layer w8: U2.10@919.84,191.2 919.84,171.16 942,149 R40.2@942,133.98
NetR41_2: R41.2 U2.11 | length 83.3
  Top Layer w8: U2.11@939.53,191.2 939.53,173.47 956,157 972,157 980,149 R41.2@980,133.98
NetR42_2: R42.2 U2.12 | length 99.3
  Top Layer w8: U2.12@959.21,191.2 959.21,183.79 970,173 1001,173 1017,157 R42.2@1017,133.98
NetR43_2: R43.2 U2.13 | length 49.5
  Top Layer w8: U2.13@984.8,216.79 995.72,216.79 R43.2@1023.01,189.5
NetR46_2: R46.2 U2.14 | length 42.8
  Top Layer w8: U2.14@984.8,236.47 1002.53,236.47 1013.5,225.5 R46.2@1023.01,225.5
NetR47_2: R47.2 U2.15 | length 40.4
  Top Layer w8: U2.15@984.8,256.16 1017.67,256.16 R47.2@1023.01,261.5
NetR49_2: R49.2 U2.16 | length 47.8
  Top Layer w8: U2.16@984.8,275.84 999.86,275.84 R49.2@1023.02,299
nLED: J3.1 J9.16 R72.1 U11.3 | length 1487.2
  Top Layer w15: U11.3@1433.95,1771.2 1433.95,1807.95 v1(1435,1809) 1461.06,1835.06 J3.1@2049.95,1835.06 v1(2175,1835.06) J3.1@2294.05,1835.06
  Bottom Layer w15: v1(1435,1809) 1467.77,1776.23 R72.1@1495.52,1776.23 ; J9.16@1993,1445.22 1993,1721 2107.06,1835.06 v1(2175,1835.06)
PG_1V1: J12.10 R20.2 R41.1 TP16.1 U10.8 | length 4755.1
  Top Layer w8: v1(464,1453) 412,1401 412,511 456,467 456,70 501,25 952,25 v1(980,53) R41.1@980,108 ; v1(584,1472) 584,1400 TP16.1@583,1399 583,1383 592.99,1373.01 R20.2@633,1373.01 699.04,1373.01 U10.8@700.47,1371.57
  Bottom Layer w8: v1(464,1453) 483,1472 v1(584,1472) ; v1(980,53) 1995.36,53 2242.95,300.59 2242.95,812.05 2199,856 1881,856 1843,818 J12.10@1843,745.22
PG_1V2: R16.2 R36.1 TP14.1 U4.6 | length 1704.6
  Top Layer w8: v1(475,1137.5) 475,1136 451,1112 451,533 496,488 496,173 542.52,126.48 724.52,126.48 779,72 848,72 848,73 859,84 R36.1@859,108.5
  Top Layer w10: v1(578,1138) TP14.1@578,1067 594.99,1050.01 R16.2@624,1050.01 624.13,1050.13 U4.6@673.31,1050.13
  Bottom Layer w8: v1(475,1137.5) 577.5,1137.5 v1(578,1138)
PG_1V8: J12.14 R6.2 R31.1 TP5.1 U6.6 | length 4432
  Top Layer w8: U6.6@676.31,1778.13 663.87,1778.13 648,1794 589,1794 TP5.1@583,1800 545,1800 529,1784 529,611 566,574 622,574 681,515 681,265 v1(708,238) 713.5,238 722,246.5 R31.1@768,246.5
  Bottom Layer w8: v1(708,238) 708,110 772,46 929,46 959,76 1924,76 2195.95,347.95 2195.95,791.05 2160,827 1971,827 1942,798 J12.14@1942,737
PG_1V35: J12.12 R12.2 R34.1 TP10.1 U8.6 | length 3555.3
  Top Layer w8: v1(472,1540) 472,1484 499,1457 499,554 528,525 629,525 650,504 650,232 707,175 R34.1@768.01,175
  Top Layer w10: v1(1768,874) 1833,809 v1(1893,809)
  Top Layer w12: v1(1236,1512) 1280,1468 TP10.1@1280,1442 1294.99,1427.01 R12.2@1325,1427.01 1325,1420 v1(1347,1398) 1368.31,1419.31 U8.6@1368.31,1427.13
  Bottom Layer w8: v1(472,1540) 1208,1540 v1(1236,1512)
  Bottom Layer w10: v1(1347,1398) 1355,1390 1355,1171.63 1543.63,983 1659,983 v1(1768,874) ; J12.12@1893,745.22 v1(1893,809)
PG_3V3: J12.16 R3.2 R24.1 TP3.1 U3.8 | length 3130.8
  Top Layer w8: TP3.1@599,785 599,767 609.99,756.01 R3.2@647,756.01 676.99,756.01 v1(685,748) 692.08,755.08 U3.8@724.23,755.08
  Top Layer w10: TP3.1@599,767 561,729 561,629 578,612 625.21,612 713,524.21 713,356 v1(735,334) 752.49,334 R24.1@767.99,318.5
  Bottom Layer w8: v1(735,334) 708,307 708,270.53 751,227.53 751,99.2 785.2,65 925,65 1004,144 1573,144 1624.26,92.74 1914.74,92.74 2173,351 2173,595 2119,649 2018,649 1993,674 J12.16@1993,745.22
pLED: C44.1 D1.1 J3.2 J9.15 | length 1645.3
  Top Layer w15: D1.1@1495.52,1762.45 1551.95,1762.45 C44.1@1566,1776.5 1891.5,1776.5 v1(1950,1718) 1951.06,1716.94 J3.2@2049.95,1716.94 J3.2@2294.05,1716.94
  Bottom Layer w15: J9.15@1993,1222.78 1993,1182 2035,1140 2148,1140 2184,1176 2184,1690 v1(2211,1717)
